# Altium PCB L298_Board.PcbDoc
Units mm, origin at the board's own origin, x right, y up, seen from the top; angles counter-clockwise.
Board outline 35.56 x 35.56 mm, 2 copper layers (Top Layer, Bottom Layer); 20 components, 15 nets, 72 pads, 39 vias.
Unrouted connection lines stored in the file: 18.
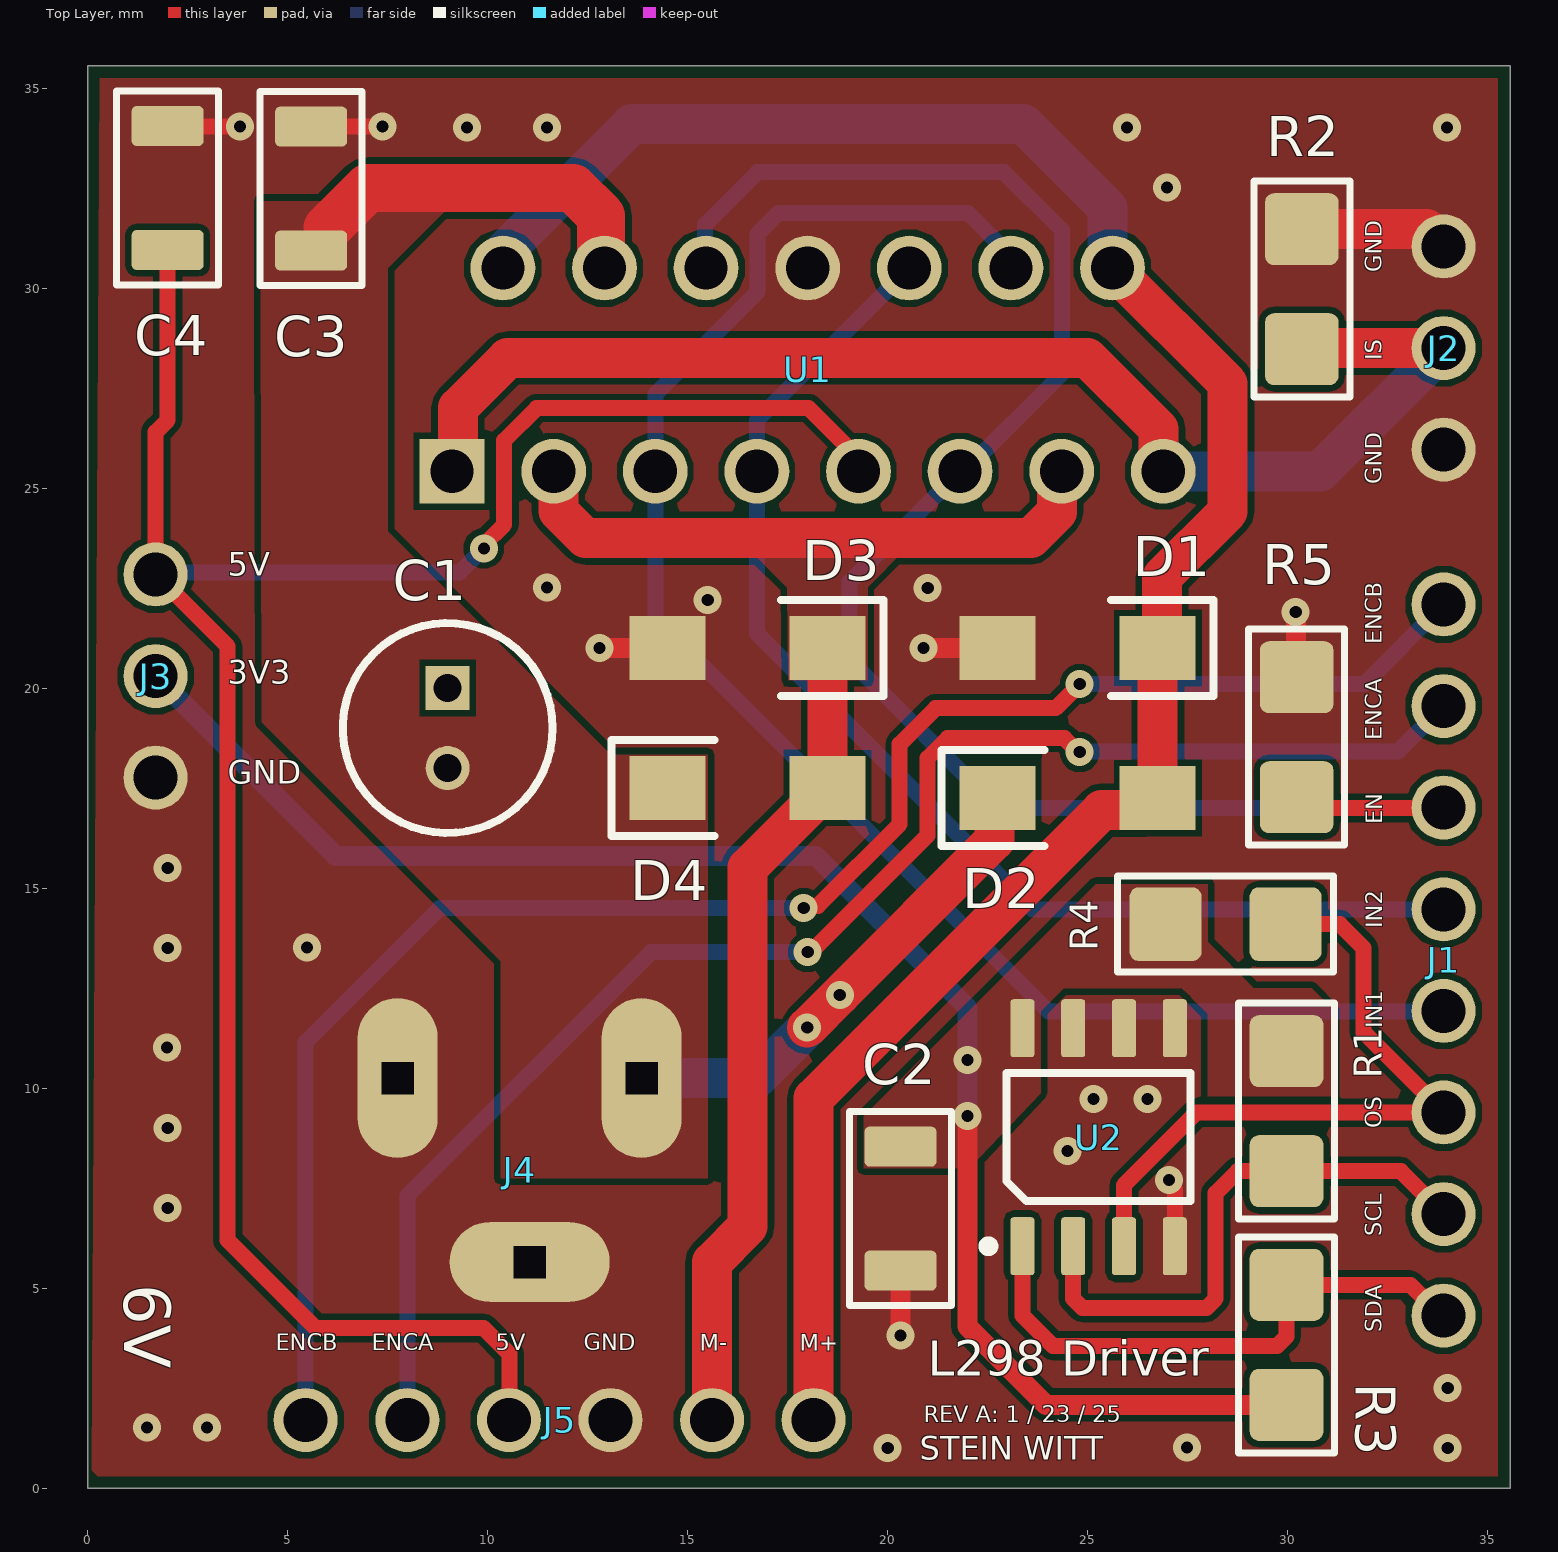
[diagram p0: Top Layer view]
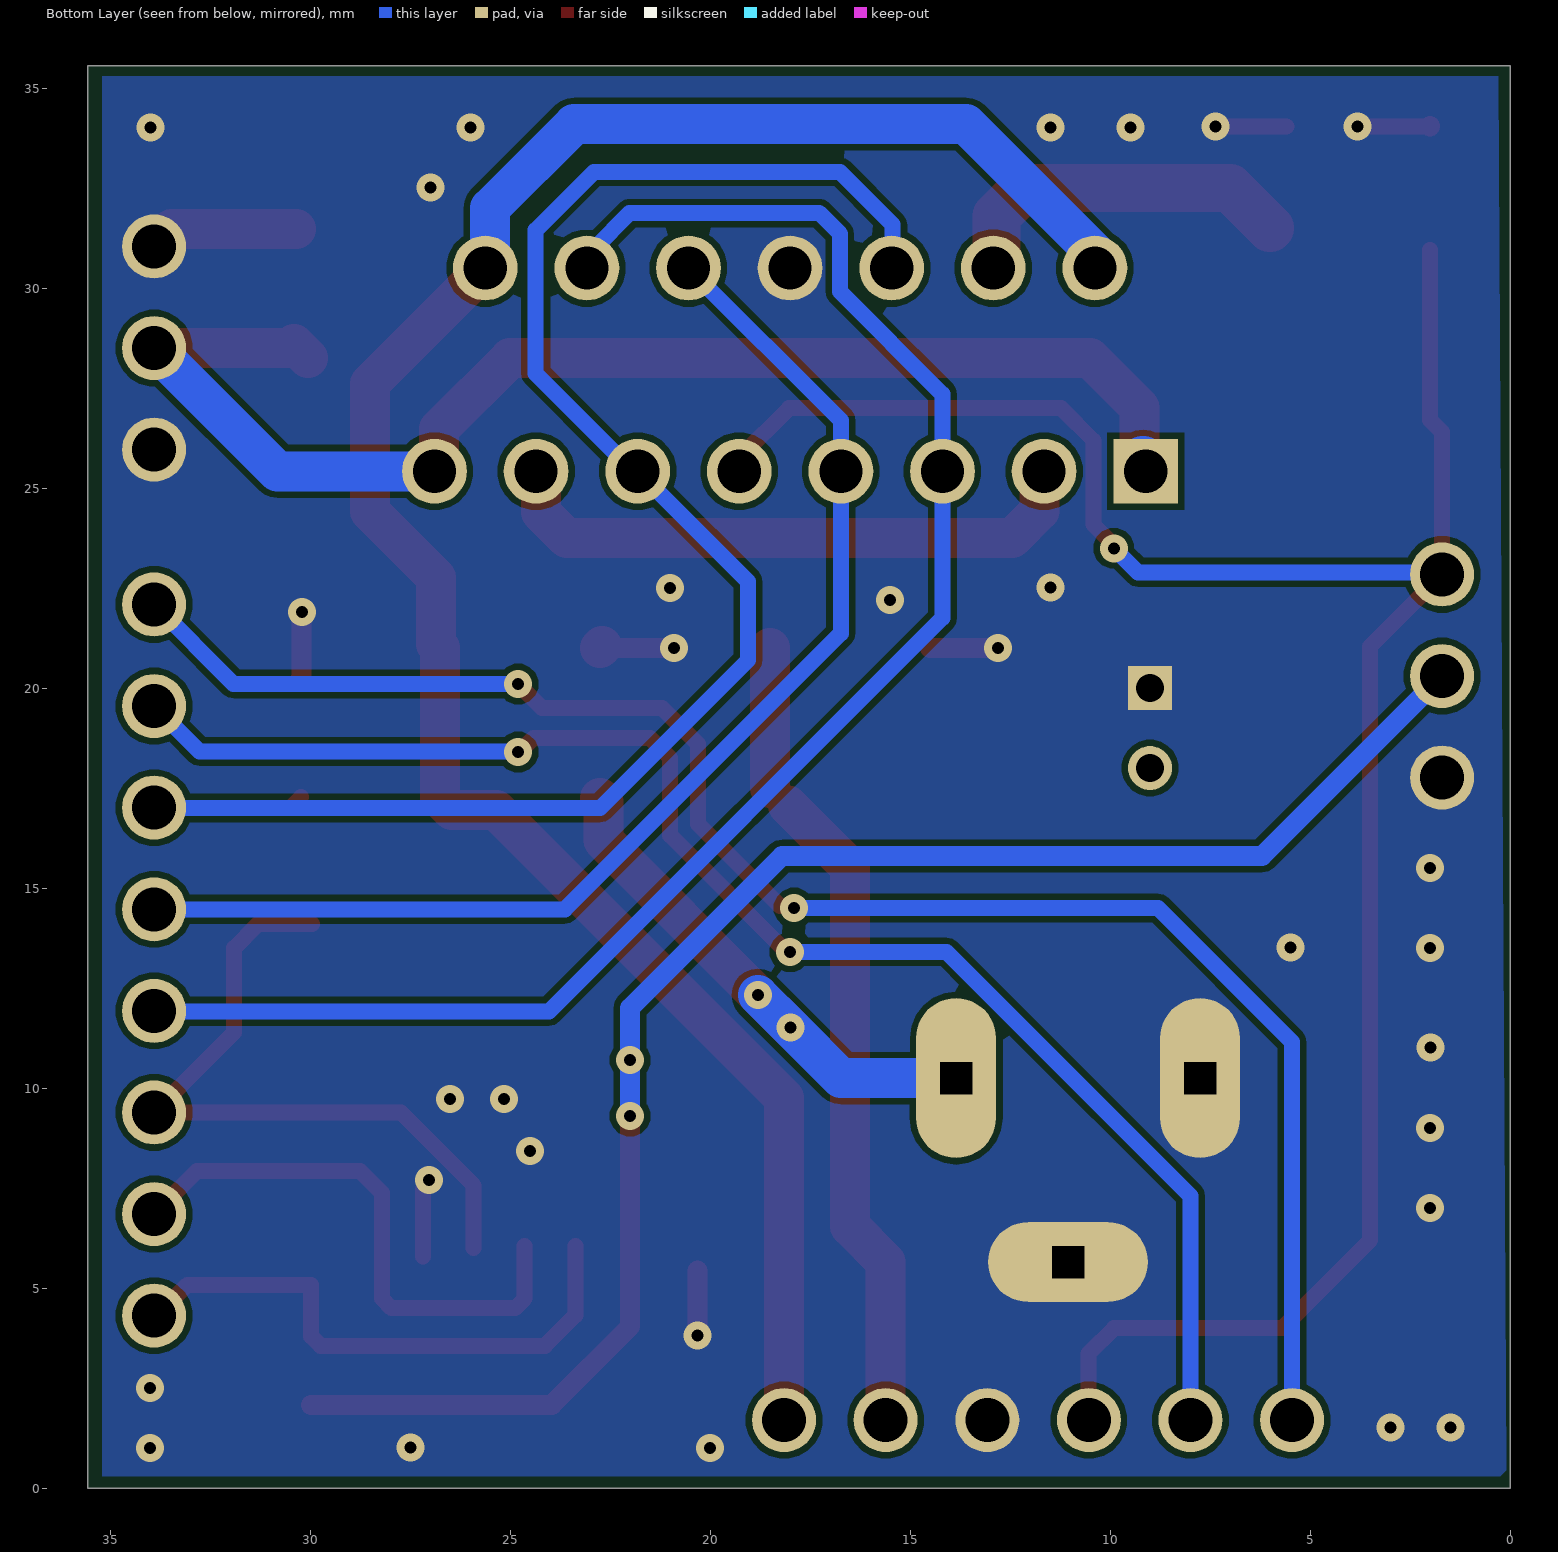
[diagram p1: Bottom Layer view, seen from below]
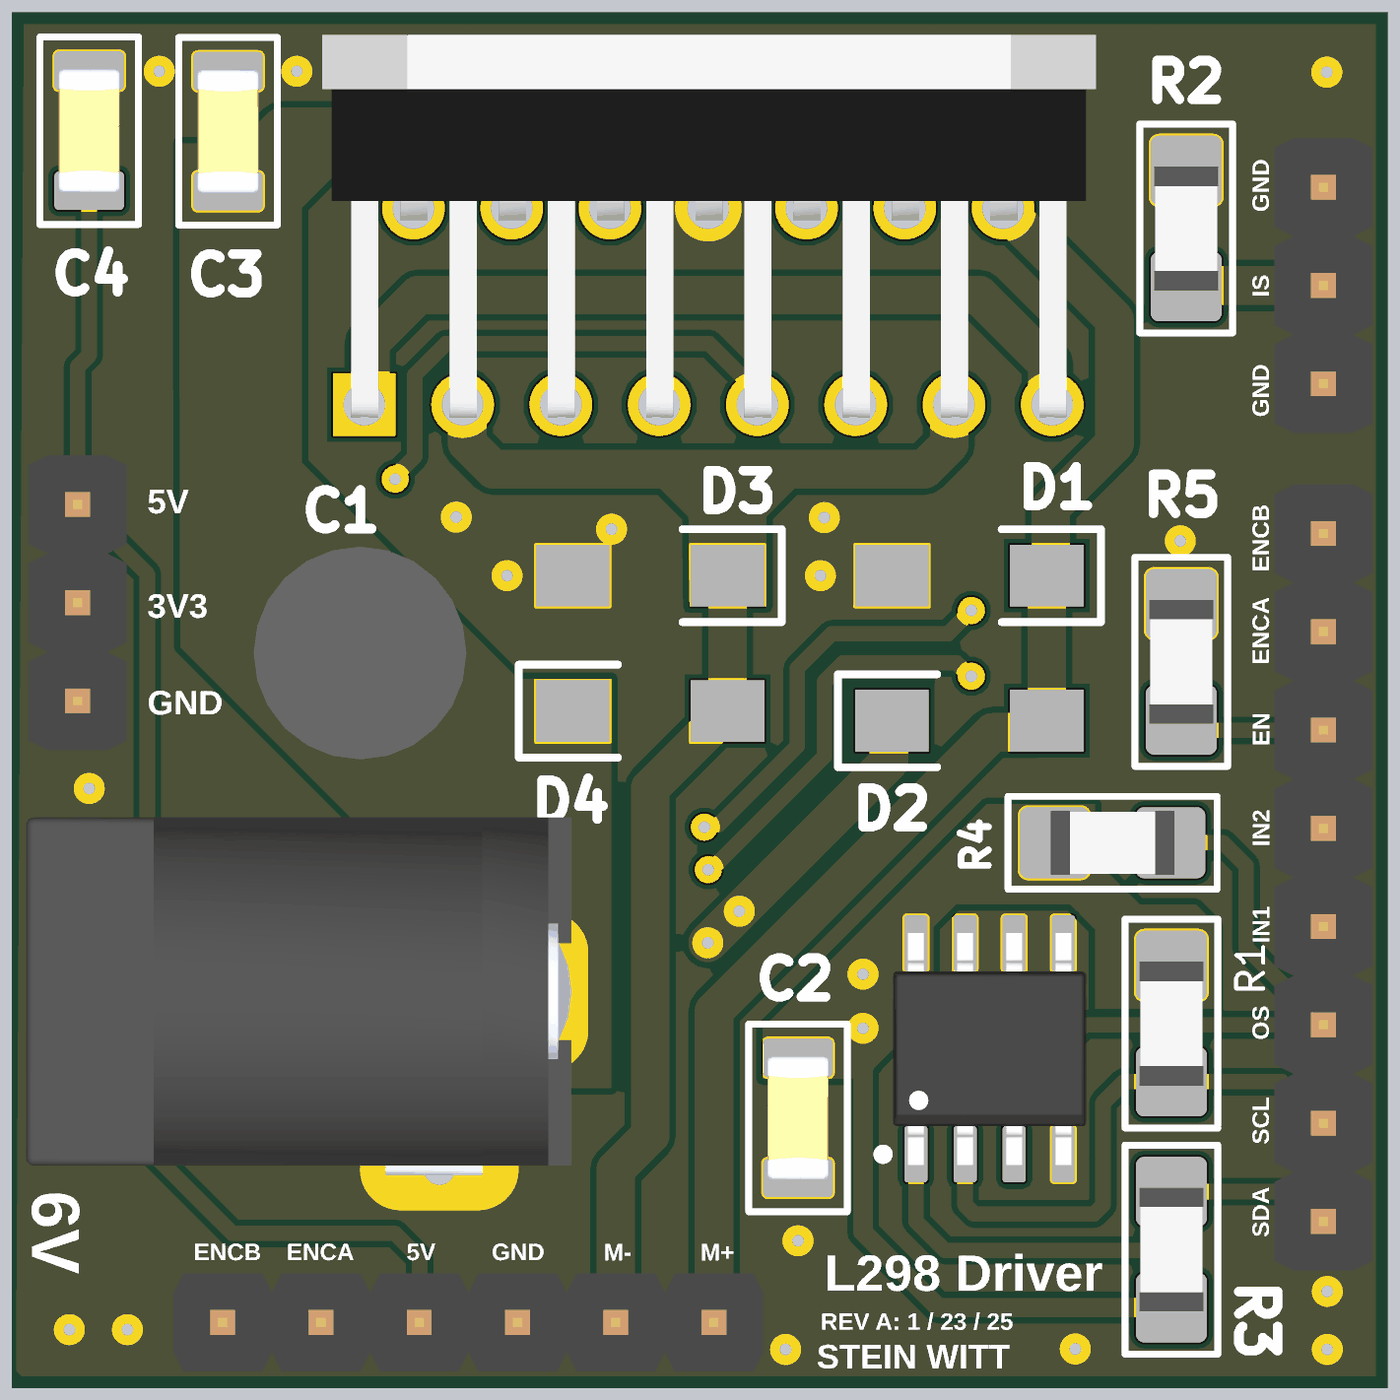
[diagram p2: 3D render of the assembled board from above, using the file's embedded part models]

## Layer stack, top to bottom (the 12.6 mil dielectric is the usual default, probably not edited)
Top Solder: solder mask 0.0102, Solder Resist, Dk 3.5
Top Layer: signal copper 0.0356
Dielectric 1: dielectric 0.32, FR-4, Dk 4.8
Bottom Layer: signal copper 0.0356
Bottom Solder: solder mask 0.0102, Solder Resist, Dk 3.5

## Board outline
0,0 35.56,0 35.56,35.56 0,35.56

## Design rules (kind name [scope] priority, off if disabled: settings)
Clearance [All] p1: gap=0.152 ignorepadtopadclearanceinfootprint=FALSE
HoleSize [All] p1: absolutevalues=TRUE maxlimit=4 minlimit=0.025 maxpercent=80.000 minpercent=20.000
MinimumAnnularRing [All] p1: minimumring=0.127
PlaneClearance [All] p1: clearance=0.5
PolygonConnect [All] p1: connectstyle=Direct reliefconductorwidth=0.254 reliefentries=4 polygonreliefangle="90 Angle" airgapwidth=0.254
RoutingVias [All] p1: holewidth=0.305 width=0.61 viastyle="Through Hole" minholewidth=0.254 minwidth=0.508 maxholewidth=1.27 maxwidth=2.54
SilkToSolderMaskClearance [IsPad] p1: minsilkscreentomaskgap=0.041 clearancetoexposedcopper=TRUE
SolderMaskExpansion [All] p1: expansion=0.051 istentingtop=FALSE
SupplyNets "Schematic Supply Nets_3" [InNet('3V3')] p1: voltage=0.000
SupplyNets "Schematic Supply Nets_2" [InNet('GND')] p2: voltage=0.000
SupplyNets "Schematic Supply Nets_1" [InNet('5V')] p3: voltage=0.000
SupplyNets "Schematic Supply Nets" [InNet('6V')] p4: voltage=0.000
Width [All] p1: maxlimit=2 minlimit=0.152 preferedwidth=0.254 minimp=50.000000 maximp=50.000000 favimp=50.000000
27 further rules are at their usual default settings.

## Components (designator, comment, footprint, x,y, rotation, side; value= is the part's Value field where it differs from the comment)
C1 "REA010M2CBK-0511P" CAP_TH_RADIAL_0511 9,20 r270 top value=1uF
C2 "C1206C104K5RAC7800" CAP_1206 20.32,6.985 r90 top
C3 "C1206C104K5RAC7800" CAP_1206 5.588,32.486 r270 top
C4 "C1206C104K5RAC7800" CAP_1206 2,32.5 r90 top
D1 "RS2AA R3G" RS2AA 24.75,21 r180 top
D2 "RS2AA R3G" RS2AA 24.75,17.25 r0 top
D3 "RS2AA R3G" RS2AA 16.5,21 r180 top
D4 "RS2AA R3G" RS2AA 16.5,17.5 r0 top
J1 "8 Pin Male Connector" "8 PIN THT HEADER" 33.9,13.2 r270 top
J2 "3 Pin 2.54mm Male Connector" "3 PIN THT HEADER" 33.9,28.5 r270 top
J3 "3 Pin 2.54mm Male Connector" "3 PIN THT HEADER" 1.7,20.3 r90 top
J4 "Barrel Jack" GRAVITECH_CON-SOCJ-2155 7.75,10.25 r0 top
J5 "Motor_Header" "6 PIN THT HEADER" 11.8,1.7 r180 top
R1 "RC1206JR-0710KL" RES_1206 29.972,9.422 r270 top value=10k
R2 "RL1206FR-070R04L" RES_1206 30.353,29.972 r270 top value=40M
R3 "RC1206JR-0710KL" RES_1206 29.972,3.58 r90 top value=10k
R4 "RC1206JR-0710KL" RES_1206 28.448,14.097 r180 top value=10k
R5 "RC1206JR-0710KL" RES_1206 30.226,18.772 r270 top value=10k
U1 "L298N" L298N 9.11,25.42 r90 top
U2 "LM75AIMXNOPB" SOIC8 25.273,8.77 r90 top

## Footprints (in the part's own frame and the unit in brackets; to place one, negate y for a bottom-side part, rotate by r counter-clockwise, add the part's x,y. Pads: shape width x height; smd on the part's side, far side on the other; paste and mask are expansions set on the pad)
"3 PIN THT HEADER" [mm] "Pin Header, pitch 2.54 mm, THT, Vertical, single row, 3p"
  round 1.6 hole 1.1: 1(-2.54,0) 2(0,0) 3(2.54,0)
  body extent -3.81,-1.27 3.81,1.27, height 8.57
"6 PIN THT HEADER" [mm] "Pin Header, pitch 2.54 mm, THT, Vertical, single row, 6p"
  round 1.6 hole 1.1: 1(-6.35,0) 2(-3.81,0) 3(-1.27,0) 4(1.27,0) 5(3.81,0) 6(6.35,0)
  body extent -7.62,-1.27 7.62,1.27, height 8.57
"8 PIN THT HEADER" [mm] "Pin Header, pitch 2.54 mm, THT, Vertical, single row, 8p"
  round 1.6 hole 1.1: 1(-8.89,0) 2(-6.35,0) 3(-1.27,0) 4(1.27,0) 5(-3.81,0) 6(3.81,0) 7(8.89,0) 8(6.35,0)
  body extent -10.16,-1.27 10.16,1.27, height 8.57
CAP_1206 [mm]
  rrect25% 1x1.8 smd: 1(-1.55,0) 2(1.55,0)
  silkscreen extent -2.42,-1.28 2.42,1.28, body extent -1.6,-0.8 1.6,0.8, height 0.94
CAP_TH_RADIAL_0511 [mm]
  rect 1.1x1.1 / inner round 1.1 / far side rect 1.1x1.1 hole 0.7: 1(0,0)
  round 1.1 hole 0.7: 2(2,0)
  silkscreen extent -1.62,-2.62 3.62,2.63, body extent -1.74,-2.75 3.75,2.75, height 12.5
GRAVITECH_CON-SOCJ-2155 [mm]
  oval 2x4 hole 0.8 square: 1(6.1,0) 3(0,0)
  oval 4x2 hole 0.8 square: 2(3.3,-4.6)
  body extent -7.38,-4.75 6.72,4.5, height 11.1
L298N [mm]
  rect 1.62x1.62 hole 1.08: 1(0,0)
  round 1.62 hole 1.08: 2(5.08,-1.27) 3(0,-2.54) 4(5.08,-3.81) 5(0,-5.08) 6(5.08,-6.35) 7(0,-7.62) 8(5.08,-8.89) 9(0,-10.16) 10(5.08,-11.43) 11(0,-12.7) 12(5.08,-13.97) 13(0,-15.24) 14(5.08,-16.51) 15(0,-17.78)
  body extent -0.33,-18.91 9.56,1.09, height 20.45
RES_1206 [mm]
  rrect25% 1.8x1.84 smd: 1(-1.5,0) 2(1.5,0)
  silkscreen extent -2.7,-1.2 2.7,1.2, body extent -1.6,-0.83 1.6,0.83, height 0.57
RS2AA [mm]
  rect 1.9x1.6 smd: 1(-2,0) 2(2,0)
  silkscreen extent -3.4,-1.2 -0.83,1.2, body extent -2.3,-1 2.3,1, height 2.5
SOIC8 [mm] "SOIC, 8-Leads, Body 4.91x3.90mm, Pitch 1.27mm, IPC Medium Density"
  rrect25% 1.45x0.6 smd: 1(-2.725,1.905) 2(-2.725,0.635) 3(-2.725,-0.635) 4(-2.725,-1.905) 5(2.725,-1.905) 6(2.725,-0.635) 7(2.725,0.635) 8(2.725,1.905)
  silkscreen extent -2.85,-2.3 1.6,2.88, body extent -3,-2.5 3,2.5, height 1.75

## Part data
C1: "Radial Leaded 160V 1.0uF 20% 5x11mm", Capacitor Type=Aluminium, Manufacturer=Lelon, Max Operating Temperature=85°C, Min Operating Temperature=-40°C, Package Style=RadialMeter, Rated DC Voltage (URdc)=160V, Ripple Current=20mA, Supplier Part Number=140-REA1R0M2CBK0511P, Tolerance  (fill in as +-)=20%
C2 C3 C4: "0.1 µF ±10% 50V Ceramic Capacitor X7R 1206 (3216 Metric)", Capacitance=100nF
D1 D2 D3 D4: "Diode Fast Recovery Rectifier 50V 1.5A 2-Pin DO-214AC Plastic T/R", Manufacturer="Taiwan Semiconductor", Supplier Part Number=RS2AAR3GCT-ND
J5: library part "6 pin 2.54mm Male Connector"
R1 R3 R4 R5: "Res Thick Film 1206 10K Ohm 5% 1/4W", Case Code (Imperial)=1206, Case Code (Metric)=3216, Manufacturer=Yageo, Max Operating Temperature=155°C, Max Power Dissipation=250mW, Min Operating Temperature=-55°C, Package Quantity=1, Resistance Tolerance=5%, Resistor Type="Thick Film", Supplier Part Number=4750733, Temperature Coefficient=100ppm/°C, Voltage Rating=200V
R2: "SMD Current Sense Resistor, 40 Milliohms, ± 1%, 250 mW, 1206 [3216 Metric], Thick Film", Case Code (Imperial)=1206, Case Code (Metric)=3216, Manufacturer=Yageo, Max Operating Temperature=155°C, Max Power Dissipation=250mW, Min Operating Temperature=-55°C, Package Quantity=5000, Ratings=AEC-Q200, Resistor Type="Thick Film", Supplier Part Number=311-.04LWCT-ND, Temperature Coefficient=1200ppm/°C, Tolerance=1%
U1: "Dual Full Bridge Motor Driver 15-Pin(15+Tab) MULTIWATT V Tube", Package=None
U2: "No Description Available", Mfr_Name="Texas Instruments"

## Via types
v1: diameter 0.7, hole 0.305, Top Layer to Bottom Layer, 27 vias
v2: diameter 0.7, hole 0.3, Top Layer to Bottom Layer, 12 vias

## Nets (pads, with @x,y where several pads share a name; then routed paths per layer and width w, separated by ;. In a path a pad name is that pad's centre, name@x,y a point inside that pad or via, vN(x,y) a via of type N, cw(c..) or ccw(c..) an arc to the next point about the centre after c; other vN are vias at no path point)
3V3: C2.2 J3.2 R1.1 R3.1 R4.2 U2.8 | length 40.5
  Top Layer w0.5: v2(22,9.3) 22,4.035 23.955,2.08 R3.1
  Bottom Layer w0.5: J3.2 6.2,15.8 18.2,15.8 22,12 v2(22,10.7) v2(22,9.3)
5V: C4.1 J3.3 J5.4 U1.9 | length 56.5
  Top Layer w0.4: C4.1 2,26.7 1.7,26.4 J3.3 3.5,21.04 3.5,6.2 5.7,4 9.9,4 10.541,3.359 J5.4@10.541,1.7 ; v2(9.906,23.495) 9.906,23.576 10.414,24.084 10.414,26.189 11.225,27 18.025,27 19.27,25.755 U1.9
  Bottom Layer w0.4: J3.3@2.105,22.895 9.306,22.895 v2(9.906,23.495)
6V: C1.2 C3.2 D2.1 D4.1 J4.1 U1.4 | length 22.4
  Top Layer w1: v1(17.988,11.511) v1(18.803,12.326) 22.669,16.192 22.669,17.17 D2.1
  Top Layer w1.2: 6,31.5 7,32.5 12.137,32.5 12.84,31.797 12.84,30.58 U1.4
  Bottom Layer w1: J4.1 16.727,10.25 v1(17.988,11.511) v1(18.803,12.326)
ENABLE: J1.5 R5.2 U1.6 U1.11 | length 43.9
  Top Layer w0.4: R5.2 30.498,17 J1.5@33.9,17
  Bottom Layer w0.4: U1.6 15.434,30.526 15.434,31.584 16.75,32.9 22.904,32.9 24.359,31.445 24.359,27.859 21.92,25.42 U1.11 19.05,22.66 19.05,20.701 22.751,17 J1.5@33.5,17
ENC_A: J1.2 J5.5 | length 38
  Top Layer w0.4: v1(18,13.4) 18.08,13.4 21,16.32 21,18.251 21.499,18.75 24.416,18.75 24.766,18.4 v1(24.8,18.4)
  Bottom Layer w0.4: J5.5 7.99,7.303 14.087,13.4 v1(18,13.4) ; v1(24.8,18.4) 24.815,18.415 32.765,18.415 J1.2
ENC_B: J1.1 J5.6 | length 43.6
  Top Layer w0.4: v1(17.9,14.5) 17.957,14.557 18.257,14.557 20.3,16.6 20.3,18.6 21.2,19.5 24.2,19.5 v1(24.8,20.1)
  Bottom Layer w0.4: J5.6 5.45,11.15 8.8,14.5 v1(17.9,14.5) ; v1(24.8,20.1) 31.91,20.1 J1.1
GND: C1.1 C2.1 C3.1 C4.2 D1.2 D3.2 J2.1 J2.3 J3.1 J4.2 J4.3 J5.3 R2.1 R5.1 U1.8 U2.4 U2.5 U2.6 U2.7 | length 16
  Top Layer w0.4: C4.2@2.007,34.043 v2@3.803,34.043 ; C3.1 v2(7.366,34.036) ; v2(27.029,7.696) 27.029,7.615 27.178,7.466 U2.4@27.178,5.791
  Top Layer w0.5: C4.2 C4.2@2.007,34.043 ; v2@3.803,34.043 v2(3.81,34.036) ; v2(12.8,21) D3.2 ; v2(20.32,3.81) C2.1 ; v2(20.9,21) 22.65,21 D1.2@22.7,21.05 ; v1(30.2,21.9) 30.213,21.887 30.213,20.285 R5.1
  Top Layer w1: D1.2@22.7,21.05 D1.2 ; R2.1 33.468,31.472 33.623,31.317 J2.1@33.623,31.04
  other v1: 20,1 27.487,1.013 34,1 1.487,1.513 2.987,1.513 34,2.5 2,7 2,9 1.987,11.013 2,13.5 5.487,13.513 2,15.5 15.5,22.2 21,22.5 11.487,22.513 26.987,32.513 9.487,34.013 11.487,34.013 25.987,34.013 33.987,34.013
  other v2: 24.5,8.425 25.15,9.725 26.5,9.725
I_SENSE: J2.2 R2.2 U1.1 U1.15 | length 34.1
  Top Layer w1: U1.1 9.261,25.571 9.261,27.011 10.5,28.25 25,28.25 26.771,26.479 26.771,25.539 U1.15 ; R2.2@30.05,28.25 R2.2@30.4,28.6 ; R2.2@30.4,28.5 J2.2
  Bottom Layer w1: U1.15 30.82,25.42 J2.2
  Bottom Layer w1.2: U1.1 9.11,25.635 U1.1@9.175,25.7
INPUT1: J1.4 U1.5 U1.12 | length 41.7
  Bottom Layer w0.4: U1.12 22.9,30.68 22.9,30.986 22.009,31.877 17.272,31.877 16.75,31.355 16.75,29.91 14.19,27.35 U1.5 14.19,21.751 24.021,11.92 J1.4@33.9,11.92
INPUT2: J1.3 U1.7 U1.10 | length 30.7
  Bottom Layer w0.4: U1.10 16.73,26.69 U1.7 16.73,21.37 23.63,14.47 J1.3
MTR_BLK: D3.1 D4.2 J5.2 U1.3 U1.13 | length 35
  Top Layer w1: U1.3 11.769,25.301 11.769,24.426 12.446,23.749 23.583,23.749 24.231,24.398 24.231,25.301 U1.13 ; J5.2 15.61,5.65 16.5,6.54 16.5,15.511 D4.2@18.05,17.061 ; D4.2 D3.1
MTR_RED: D1.1 D2.2 J5.1 U1.2 U1.14 | length 54.2
  Top Layer w1: J5.1 18.15,9.75 25.35,16.95 26.45,16.95 D2.2 D1.1 26.854,21.104 26.854,22.765 28.5,24.411 28.5,27.62 U1.14
  Bottom Layer w1: U1.2 10.38,30.88 13.6,34.1 23.4,34.1 25.501,31.999 25.501,30.619 U1.14
OS: J1.6 R4.1 U2.3 | length 17.5
  Top Layer w0.4: U2.3@25.908,6 U2.3 25.908,7.569 27.729,9.39 J1.6 31.9,11.39 31.9,13.5 31.303,14.097 R4.1
SCL: J1.8 R1.2 U2.2 | length 14.1
  Top Layer w0.4: U2.2 24.638,4.734 24.872,4.5 27.966,4.5 28.2,4.734 28.2,7.372 28.75,7.922 R1.2 32.828,7.922 J1.8
SDA: J1.7 R3.2 U2.1 | length 14.3
  Top Layer w0.4: U2.1 23.368,4.318 24.13,3.556 29.738,3.556 29.972,3.79 R3.2 33.066,5.08 33.836,4.31 J1.7

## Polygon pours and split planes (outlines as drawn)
GND on Top Layer "GND_L01_P008" (solid, pour order 8): 0.308,35.25 35.25,35.25 35.25,0.3 0.107,0.3
3V3 on Top Layer "3V3_L01_P004" (solid, pour order 4): 22.043,8 23.825,9.871 23.825,11.925 24.4,12.5 27.353,12.5 28,11.853 28,9.8 31.14,9.8 31.14,11.96 30.6,12.5 29.156,12.5 28,13.656 28,15.1 25.2,15.1 19.4,9.3 19.4,8
6V on Top Layer "6V_L01_P000" (solid, pour order 0): 13.081,18.338 7.5,23.919 7.5,30.5 9,32 9,32.25 7.575,32.25 7.5,32.175 4.325,32.175 4.325,30.075 4.349,19.151 10.325,13.175 10.325,7.75 15.5,7.75 15.5,18.338
GND on Top Layer "GND_L01_P005" (solid, pour order 5): 24.3,12.225 27.5,12.225 27.5,9.7 25.5,7.7 23.3,7.7 23.3,8.5 24.3,9.5
MTR_BLK on Top Layer "MTR_BLK_L01_P003" (solid, pour order 3): 17.514,20.2 19.5,20.2 19.5,22.525 20.43,23.455 20.43,24.2 16.525,24.2 16.525,23.475 17.487,22.513
GND on Bottom Layer "GND_L02_P006" (solid, pour order 6): 0.299,35.3 35.2,35.3 35.2,0.3 0.099,0.3

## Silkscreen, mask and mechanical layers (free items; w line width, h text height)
Top Overlay:
  text "GND" at 32.492,30.4 h0.7 r90
  text "IS" at 32.492,28.2 h0.7 r90
  text "GND" at 32.492,25.1 h0.7 r90
  text "5V" at 3.5,22.612 h1
  text "ENCB" at 32.492,21.1 h0.7 r90
  text "3V3" at 3.5,19.912 h1
  text "ENCA" at 32.492,18.7 h0.7 r90
  text "GND" at 3.5,17.412 h1
  text "EN" at 32.5,16.6 h0.7 r90
  text "IN2" at 32.5,14 h0.7 r90
  text "IN1" at 32.5,11.5 h0.7 r90
  text "OS" at 32.492,9 h0.7 r90
  text "SCL" at 32.492,6.3 h0.7 r90
  text "6V" at 0.524,5.1 h2 r270
  text "SDA" at 32.492,3.9 h0.7 r90
  text "ENCB" at 4.7,3.308 h0.7
  text "ENCA" at 7.1,3.308 h0.7
  text "5V" at 10.2,3.308 h0.7
  text "GND" at 12.4,3.308 h0.7
  text "M-" at 15.3,3.3 h0.7
  text "M+" at 17.8,3.3 h0.7
  text "L298 Driver" at 21,2.518 h1.5
  text "REV A: 1 / 23 / 25" at 20.9,1.508 h0.7
  text "STEIN WITT" at 20.8,0.512 h1
Mechanical 5:
  the board outline again, w0.013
